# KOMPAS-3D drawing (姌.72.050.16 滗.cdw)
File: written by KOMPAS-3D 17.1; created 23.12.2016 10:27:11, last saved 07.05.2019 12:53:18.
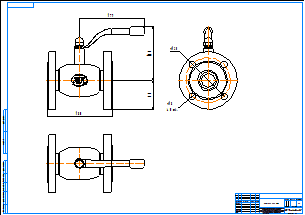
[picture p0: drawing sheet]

Sheet 1: A1, landscape

Title block, sheet 1: name: КШ.72.050.16 фф; material: Внимание! Данный продукт является объектом авторского права ООО «Торговый Дом АДЛ». / Запрещается изменение, копирование, распространение / (в том числе путем копирования на другие сайты и ресурсы в Интернете) / или любое иное использование информации и объектов без предварительного / согласия правообладателя (ООО «Торговый Дом АДЛ»).; sheets: 1; organisation: ООО "Торговый дом АДЛ"; sheet format: A1; stored path: C:\Users\tra\Desktop\2д чертежи\Шаровые краны БИВАЛ\КШ_Бивал_серия_72\KOMPAS_2D\КШ.72.050.16 фф.cdw

Views: Спереди 4, Проекционный вид 5, Проекционный вид 6
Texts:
  Klimkovich
  ADL
Dimensions and other numbers on the sheet: 180; 179; 148; 80; 125; 18; 4 Отв.; 1:1; 1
